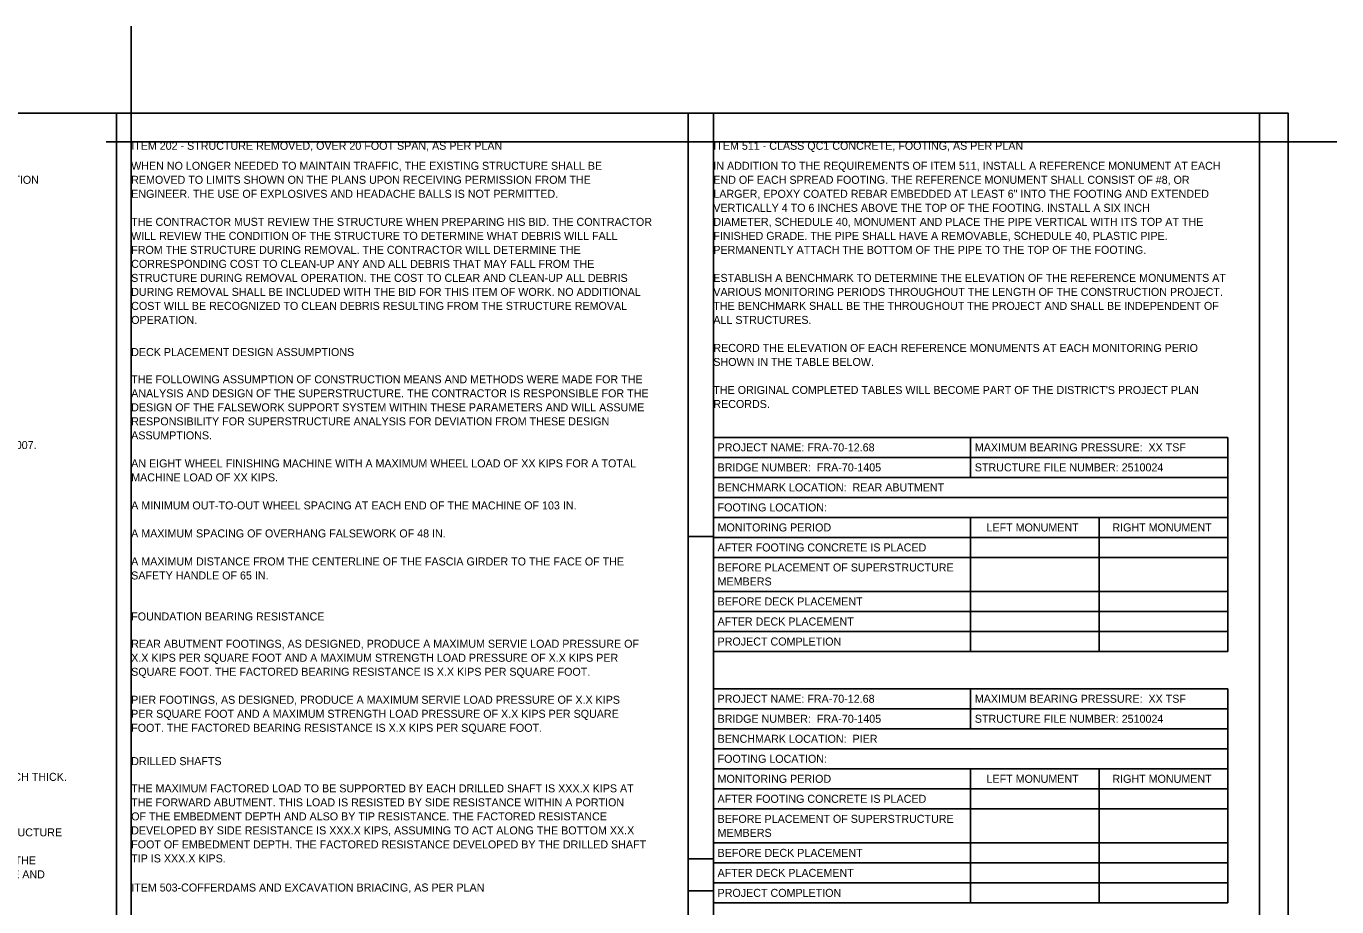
# Model space of a CAD drawing. Extents: x 1530552 to 1530730, y 675304 to 675366.
# Drawn here: x 1530563.61 to 1530586.54, y 675332.48 to 675347.87 of the extents above; entities that cross this region are included whole.
import ezdxf

# ---------------------------------------------------------------- set-up
doc = ezdxf.new("R2010")
doc.units = 0
for name, color, linetype in [('BR_P_Beam_Object', 7, 'Continuous'), ('BR_P_Gen_Text', 7, 'Continuous'), ('SC_Scratch1', 7, 'Continuous'), ('SC_Scratch2', 7, 'Continuous'), ('SC_Scratch3', 7, 'Continuous')]:
    doc.layers.add(name, color=color, linetype=linetype)

msp = doc.modelspace()

# ---------------------------------------------------------------- linework, layer by layer
at = {"layer": 'BR_P_Beam_Object'}
msp.add_line((1530565.447, 675345.853), (1530565.447, 675345.853), dxfattribs=at)
at = {"layer": 'BR_P_Gen_Text'}
for p, q in [((1530575.631, 675340.684), (1530584.631, 675340.684)), ((1530575.631, 675340.684), (1530575.631, 675336.939)), ((1530580.131, 675340.684), (1530580.131, 675339.984)), ((1530584.631, 675340.684), (1530584.631, 675336.939)), ((1530575.631, 675340.334), (1530584.631, 675340.334)), ((1530575.631, 675339.984), (1530584.631, 675339.984)), ((1530575.631, 675339.634), (1530584.631, 675339.634)), ((1530575.631, 675339.284), (1530584.631, 675339.284)), ((1530580.131, 675339.284), (1530580.131, 675336.939)), ((1530582.381, 675339.284), (1530582.381, 675336.939)), ((1530575.631, 675338.934), (1530584.631, 675338.934)), ((1530575.631, 675338.584), (1530584.631, 675338.584)), ((1530575.631, 675337.989), (1530584.631, 675337.989)), ((1530575.631, 675337.639), (1530584.631, 675337.639)), ((1530575.631, 675337.289), (1530584.631, 675337.289)), ((1530575.631, 675336.939), (1530584.631, 675336.939)), ((1530575.631, 675336.288), (1530584.631, 675336.288)), ((1530575.631, 675336.288), (1530575.631, 675332.543)), ((1530580.131, 675336.288), (1530580.131, 675335.588)), ((1530584.631, 675336.288), (1530584.631, 675332.543)), ((1530575.631, 675335.938), (1530584.631, 675335.938)), ((1530575.631, 675335.588), (1530584.631, 675335.588)), ((1530575.631, 675335.238), (1530584.631, 675335.238)), ((1530575.631, 675334.888), (1530584.631, 675334.888)), ((1530580.131, 675334.888), (1530580.131, 675332.543)), ((1530582.381, 675334.888), (1530582.381, 675332.543)), ((1530575.631, 675334.538), (1530584.631, 675334.538)), ((1530575.631, 675334.188), (1530584.631, 675334.188)), ((1530575.631, 675333.593), (1530584.631, 675333.593)), ((1530575.631, 675333.243), (1530584.631, 675333.243)), ((1530575.631, 675332.893), (1530584.631, 675332.893)), ((1530575.631, 675332.543), (1530584.631, 675332.543))]:
    msp.add_line(p, q, dxfattribs=at)
msp.add_lwpolyline([(1530555.188, 675346.353), (1530585.688, 675346.353), (1530585.688, 675325.353), (1530555.188, 675325.353)], close=True, dxfattribs=at)
at = {"layer": 'SC_Scratch1'}
msp.add_line((1530565.447, 675345.853), (1530565.447, 675345.503), dxfattribs=at)
at = {"layer": 'SC_Scratch2'}
for p, q in [((1530565.447, 675345.853), (1530565.01, 675345.853)), ((1530575.631, 675338.948), (1530575.194, 675338.948)), ((1530575.631, 675333.313), (1530575.194, 675333.313)), ((1530575.631, 675332.753), (1530575.194, 675332.753))]:
    msp.add_line(p, q, dxfattribs=at)
at = {"layer": 'SC_Scratch3'}
for p, q in [((1530565.447, 675321.188), (1530565.447, 675347.874)), ((1530565.188, 675325.353), (1530565.188, 675346.353)), ((1530575.189, 675325.353), (1530575.189, 675346.353)), ((1530575.631, 675325.636), (1530575.631, 675346.353)), ((1530585.188, 675346.353), (1530585.188, 675325.353)), ((1530565.447, 675345.853), (1530586.537, 675345.853))]:
    msp.add_line(p, q, dxfattribs=at)

# ---------------------------------------------------------------- texts
at = {"layer": 'BR_P_Gen_Text'}
for s, p in [('ITEM 202 - STRUCTURE REMOVED, OVER 20 FOOT SPAN, AS PER PLAN', (1530565.447, 675345.713)), ('ITEM 511 - CLASS QC1 CONCRETE, FOOTING, AS PER PLAN', (1530575.631, 675345.713)), ('WHEN NO LONGER NEEDED TO MAINTAIN TRAFFIC, THE EXISTING STRUCTURE SHALL BE ', (1530565.447, 675345.363)), ('IN ADDITION TO THE REQUIREMENTS OF ITEM 511, INSTALL A REFERENCE MONUMENT AT EACH ', (1530575.631, 675345.363)), ('ADOPTED BY THE AMERICAN ASSOCIATION OF STATE HIGHWAY AND TRANSPORTATION ', (1530555.688, 675345.118)), ('REMOVED TO LIMITS SHOWN ON THE PLANS UPON RECEIVING PERMISSION FROM THE ', (1530565.447, 675345.118)), ('END OF EACH SPREAD FOOTING. THE REFERENCE MONUMENT SHALL CONSIST OF #8, OR ', (1530575.631, 675345.118)), ('ENGINEER. THE USE OF EXPLOSIVES AND HEADACHE BALLS IS NOT PERMITTED.', (1530565.447, 675344.873)), ('LARGER, EPOXY COATED REBAR EMBEDDED AT LEAST 6" INTO THE FOOTING AND EXTENDED ', (1530575.631, 675344.873)), ('VERTICALLY 4 TO 6 INCHES ABOVE THE TOP OF THE FOOTING. INSTALL A SIX INCH ', (1530575.631, 675344.628)), ('THE CONTRACTOR MUST REVIEW THE STRUCTURE WHEN PREPARING HIS BID. THE CONTRACTOR ', (1530565.447, 675344.383)), ('DIAMETER, SCHEDULE 40, MONUMENT AND PLACE THE PIPE VERTICAL WITH ITS TOP AT THE ', (1530575.631, 675344.383)), ('WILL REVIEW THE CONDITION OF THE STRUCTURE TO DETERMINE WHAT DEBRIS WILL FALL ', (1530565.447, 675344.138)), ('FINISHED GRADE. THE PIPE SHALL HAVE A REMOVABLE, SCHEDULE 40, PLASTIC PIPE. ', (1530575.631, 675344.138)), ('FROM THE STRUCTURE DURING REMOVAL. THE CONTRACTOR WILL DETERMINE THE ', (1530565.447, 675343.893)), ('PERMANENTLY ATTACH THE BOTTOM OF THE PIPE TO THE TOP OF THE FOOTING.', (1530575.631, 675343.893)), ('CORRESPONDING COST TO CLEAN-UP ANY AND ALL DEBRIS THAT MAY FALL FROM THE ', (1530565.447, 675343.648)), ('STRUCTURE DURING REMOVAL OPERATION. THE COST TO CLEAR AND CLEAN-UP ALL DEBRIS ', (1530565.447, 675343.403)), ('ESTABLISH A BENCHMARK TO DETERMINE THE ELEVATION OF THE REFERENCE MONUMENTS AT ', (1530575.631, 675343.403)), ('DURING REMOVAL SHALL BE INCLUDED WITH THE BID FOR THIS ITEM OF WORK. NO ADDITIONAL ', (1530565.447, 675343.158)), ('VARIOUS MONITORING PERIODS THROUGHOUT THE LENGTH OF THE CONSTRUCTION PROJECT. ', (1530575.631, 675343.158)), ('COST WILL BE RECOGNIZED TO CLEAN DEBRIS RESULTING FROM THE STRUCTURE REMOVAL ', (1530565.447, 675342.913)), ('THE BENCHMARK SHALL BE THE THROUGHOUT THE PROJECT AND SHALL BE INDEPENDENT OF ', (1530575.631, 675342.913)), ('OPERATION.', (1530565.447, 675342.668)), ('ALL STRUCTURES.', (1530575.631, 675342.668)), ('DECK PLACEMENT DESIGN ASSUMPTIONS', (1530565.447, 675342.106)), ('RECORD THE ELEVATION OF EACH REFERENCE MONUMENTS AT EACH MONITORING PERIO ', (1530575.631, 675342.178)), ('SHOWN IN THE TABLE BELOW.', (1530575.631, 675341.933)), ('THE FOLLOWING ASSUMPTION OF CONSTRUCTION MEANS AND METHODS WERE MADE FOR THE ', (1530565.447, 675341.629)), ('ANALYSIS AND DESIGN OF THE SUPERSTRUCTURE. THE CONTRACTOR IS RESPONSIBLE FOR THE ', (1530565.447, 675341.384)), ("THE ORIGINAL COMPLETED TABLES WILL BECOME PART OF THE DISTRICT'S PROJECT PLAN ", (1530575.631, 675341.443)), ('DESIGN OF THE FALSEWORK SUPPORT SYSTEM WITHIN THESE PARAMETERS AND WILL ASSUME ', (1530565.447, 675341.139)), ('RECORDS.', (1530575.631, 675341.198)), ('RESPONSIBILITY FOR SUPERSTRUCTURE ANALYSIS FOR DEVIATION FROM THESE DESIGN ', (1530565.447, 675340.894)), ('ASSUMPTIONS. ', (1530565.447, 675340.649)), ('DESIGN SPECIFICATIONS, ARTICLE 1.3.5 AND THE ODOT BRIDGE DESIGN MANUAL, 2007.', (1530555.688, 675340.48)), ('PROJECT NAME: FRA-70-12.68', (1530575.705, 675340.439)), ('MAXIMUM BEARING PRESSURE:  XX TSF', (1530580.205, 675340.439)), ('AN EIGHT WHEEL FINISHING MACHINE WITH A MAXIMUM WHEEL LOAD OF XX KIPS FOR A TOTAL ', (1530565.447, 675340.159)), ('MACHINE LOAD OF XX KIPS.', (1530565.447, 675339.914)), ('BRIDGE NUMBER:  FRA-70-1405', (1530575.705, 675340.089)), ('STRUCTURE FILE NUMBER: 2510024', (1530580.205, 675340.089)), ('BENCHMARK LOCATION:  REAR ABUTMENT', (1530575.705, 675339.739)), ('A MINIMUM OUT-TO-OUT WHEEL SPACING AT EACH END OF THE MACHINE OF 103 IN.', (1530565.447, 675339.424)), ('FOOTING LOCATION:', (1530575.705, 675339.389)), ('MONITORING PERIOD', (1530575.705, 675339.039)), ('LEFT MONUMENT', (1530580.41, 675339.039)), ('RIGHT MONUMENT', (1530582.612, 675339.039)), ('A MAXIMUM SPACING OF OVERHANG FALSEWORK OF 48 IN.', (1530565.447, 675338.934)), ('AFTER FOOTING CONCRETE IS PLACED', (1530575.705, 675338.689)), ('A MAXIMUM DISTANCE FROM THE CENTERLINE OF THE FASCIA GIRDER TO THE FACE OF THE ', (1530565.447, 675338.444)), ('BEFORE PLACEMENT OF SUPERSTRUCTURE', (1530575.705, 675338.339)), ('SAFETY HANDLE OF 65 IN.', (1530565.447, 675338.199)), ('MEMBERS', (1530575.705, 675338.094)), ('BEFORE DECK PLACEMENT', (1530575.705, 675337.744)), ('FOUNDATION BEARING RESISTANCE', (1530565.447, 675337.482)), ('AFTER DECK PLACEMENT', (1530575.705, 675337.394)), ('REAR ABUTMENT FOOTINGS, AS DESIGNED, PRODUCE A MAXIMUM SERVIE LOAD PRESSURE OF ', (1530565.447, 675337.005)), ('PROJECT COMPLETION', (1530575.705, 675337.044)), ('X.X KIPS PER SQUARE FOOT AND A MAXIMUM STRENGTH LOAD PRESSURE OF X.X KIPS PER ', (1530565.447, 675336.76)), ('SQUARE FOOT. THE FACTORED BEARING RESISTANCE IS X.X KIPS PER SQUARE FOOT.', (1530565.447, 675336.515)), ('PIER FOOTINGS, AS DESIGNED, PRODUCE A MAXIMUM SERVIE LOAD PRESSURE OF X.X KIPS ', (1530565.447, 675336.025)), ('PROJECT NAME: FRA-70-12.68', (1530575.705, 675336.043)), ('MAXIMUM BEARING PRESSURE:  XX TSF', (1530580.205, 675336.043)), ('PER SQUARE FOOT AND A MAXIMUM STRENGTH LOAD PRESSURE OF X.X KIPS PER SQUARE ', (1530565.447, 675335.78)), ('BRIDGE NUMBER:  FRA-70-1405', (1530575.705, 675335.693)), ('STRUCTURE FILE NUMBER: 2510024', (1530580.205, 675335.693)), ('FOOT. THE FACTORED BEARING RESISTANCE IS X.X KIPS PER SQUARE FOOT.', (1530565.447, 675335.535)), ('BENCHMARK LOCATION:  PIER', (1530575.705, 675335.343)), ('DRILLED SHAFTS', (1530565.447, 675334.952)), ('FOOTING LOCATION:', (1530575.705, 675334.993)), ('MONOLITHIC WEARING SURFACE IS ASSUMED, FOR DESIGN PURPOSES, TO BE 1 INCH THICK.', (1530555.688, 675334.677)), ('MONITORING PERIOD', (1530575.705, 675334.643)), ('LEFT MONUMENT', (1530580.41, 675334.643)), ('RIGHT MONUMENT', (1530582.612, 675334.643)), ('THE MAXIMUM FACTORED LOAD TO BE SUPPORTED BY EACH DRILLED SHAFT IS XXX.X KIPS AT ', (1530565.447, 675334.476)), ('THE FORWARD ABUTMENT. THIS LOAD IS RESISTED BY SIDE RESISTANCE WITHIN A PORTION ', (1530565.447, 675334.231)), ('AFTER FOOTING CONCRETE IS PLACED', (1530575.705, 675334.293)), ('OF THE EMBEDMENT DEPTH AND ALSO BY TIP RESISTANCE. THE FACTORED RESISTANCE ', (1530565.447, 675333.986)), ('BEFORE PLACEMENT OF SUPERSTRUCTURE', (1530575.705, 675333.943)), ('DETAILS AND DIMENSIONS SHOWN ON THESE PLANS PERTAINING TO EXISTING STRUCTURE ', (1530555.688, 675333.707)), ('DEVELOPED BY SIDE RESISTANCE IS XXX.X KIPS, ASSUMING TO ACT ALONG THE BOTTOM XX.X ', (1530565.447, 675333.741)), ('FOOT OF EMBEDMENT DEPTH. THE FACTORED RESISTANCE DEVELOPED BY THE DRILLED SHAFT ', (1530565.447, 675333.496)), ('MEMBERS', (1530575.705, 675333.698)), ('TIP IS XXX.X KIPS.', (1530565.447, 675333.251)), ('BEFORE DECK PLACEMENT', (1530575.705, 675333.348)), ('OBSERVATIONS AND MEASUREMENTS. CONSEQUENTLY, THEY ARE INDICATIVE OF THE', (1530555.688, 675333.217)), ('EXISTING AND THE PROPOSED WORK BUT THEY SHALL BE CONSIDERED TENTATIVE AND', (1530555.688, 675332.972)), ('AFTER DECK PLACEMENT', (1530575.705, 675332.998)), ('ITEM 503-COFFERDAMS AND EXCAVATION BRIACING, AS PER PLAN', (1530565.447, 675332.742)), ('PROJECT COMPLETION', (1530575.705, 675332.648))]:
    msp.add_text(s, height=0.14, dxfattribs=at).set_placement(p)

doc.saveas('drawing.dxf')
